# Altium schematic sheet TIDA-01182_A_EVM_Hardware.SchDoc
size 431 x 279 mm; Date: Not shown in title block; ApprovedBy: Not shown in title block; CheckedBy: Not shown in title block; Author: Not shown in title block; CompanyName: Not shown in title block; DrawnBy: Gordon Varney; Engineer: Not shown in title block; Organization: Not shown in title block; Address1: Not shown in title block; Address2: Not shown in title block; Address3: Not shown in title block; Address4: Not shown in title block; DocumentNumber: 1; Revision: Use project parameter SCH_Rev; SheetNumber: 4; SheetTotal: 4; PageSetup: Record=PageOptions¦CenterHorizontal=True¦CenterVertical=True¦PrintScale=1.00¦XCorrection=1.00¦YCorrection=1.00¦PrintKind=0¦BorderSize=5000000¦LeftOffset=0¦BottomOffset=0¦Orientation=2¦PaperLength=1000¦PaperWidth=1000¦Scale=100¦PaperSource=15¦PrintQuality=600¦MediaType=1¦DitherType=10¦PaperKind=Letter¦PrintScaleMode=1
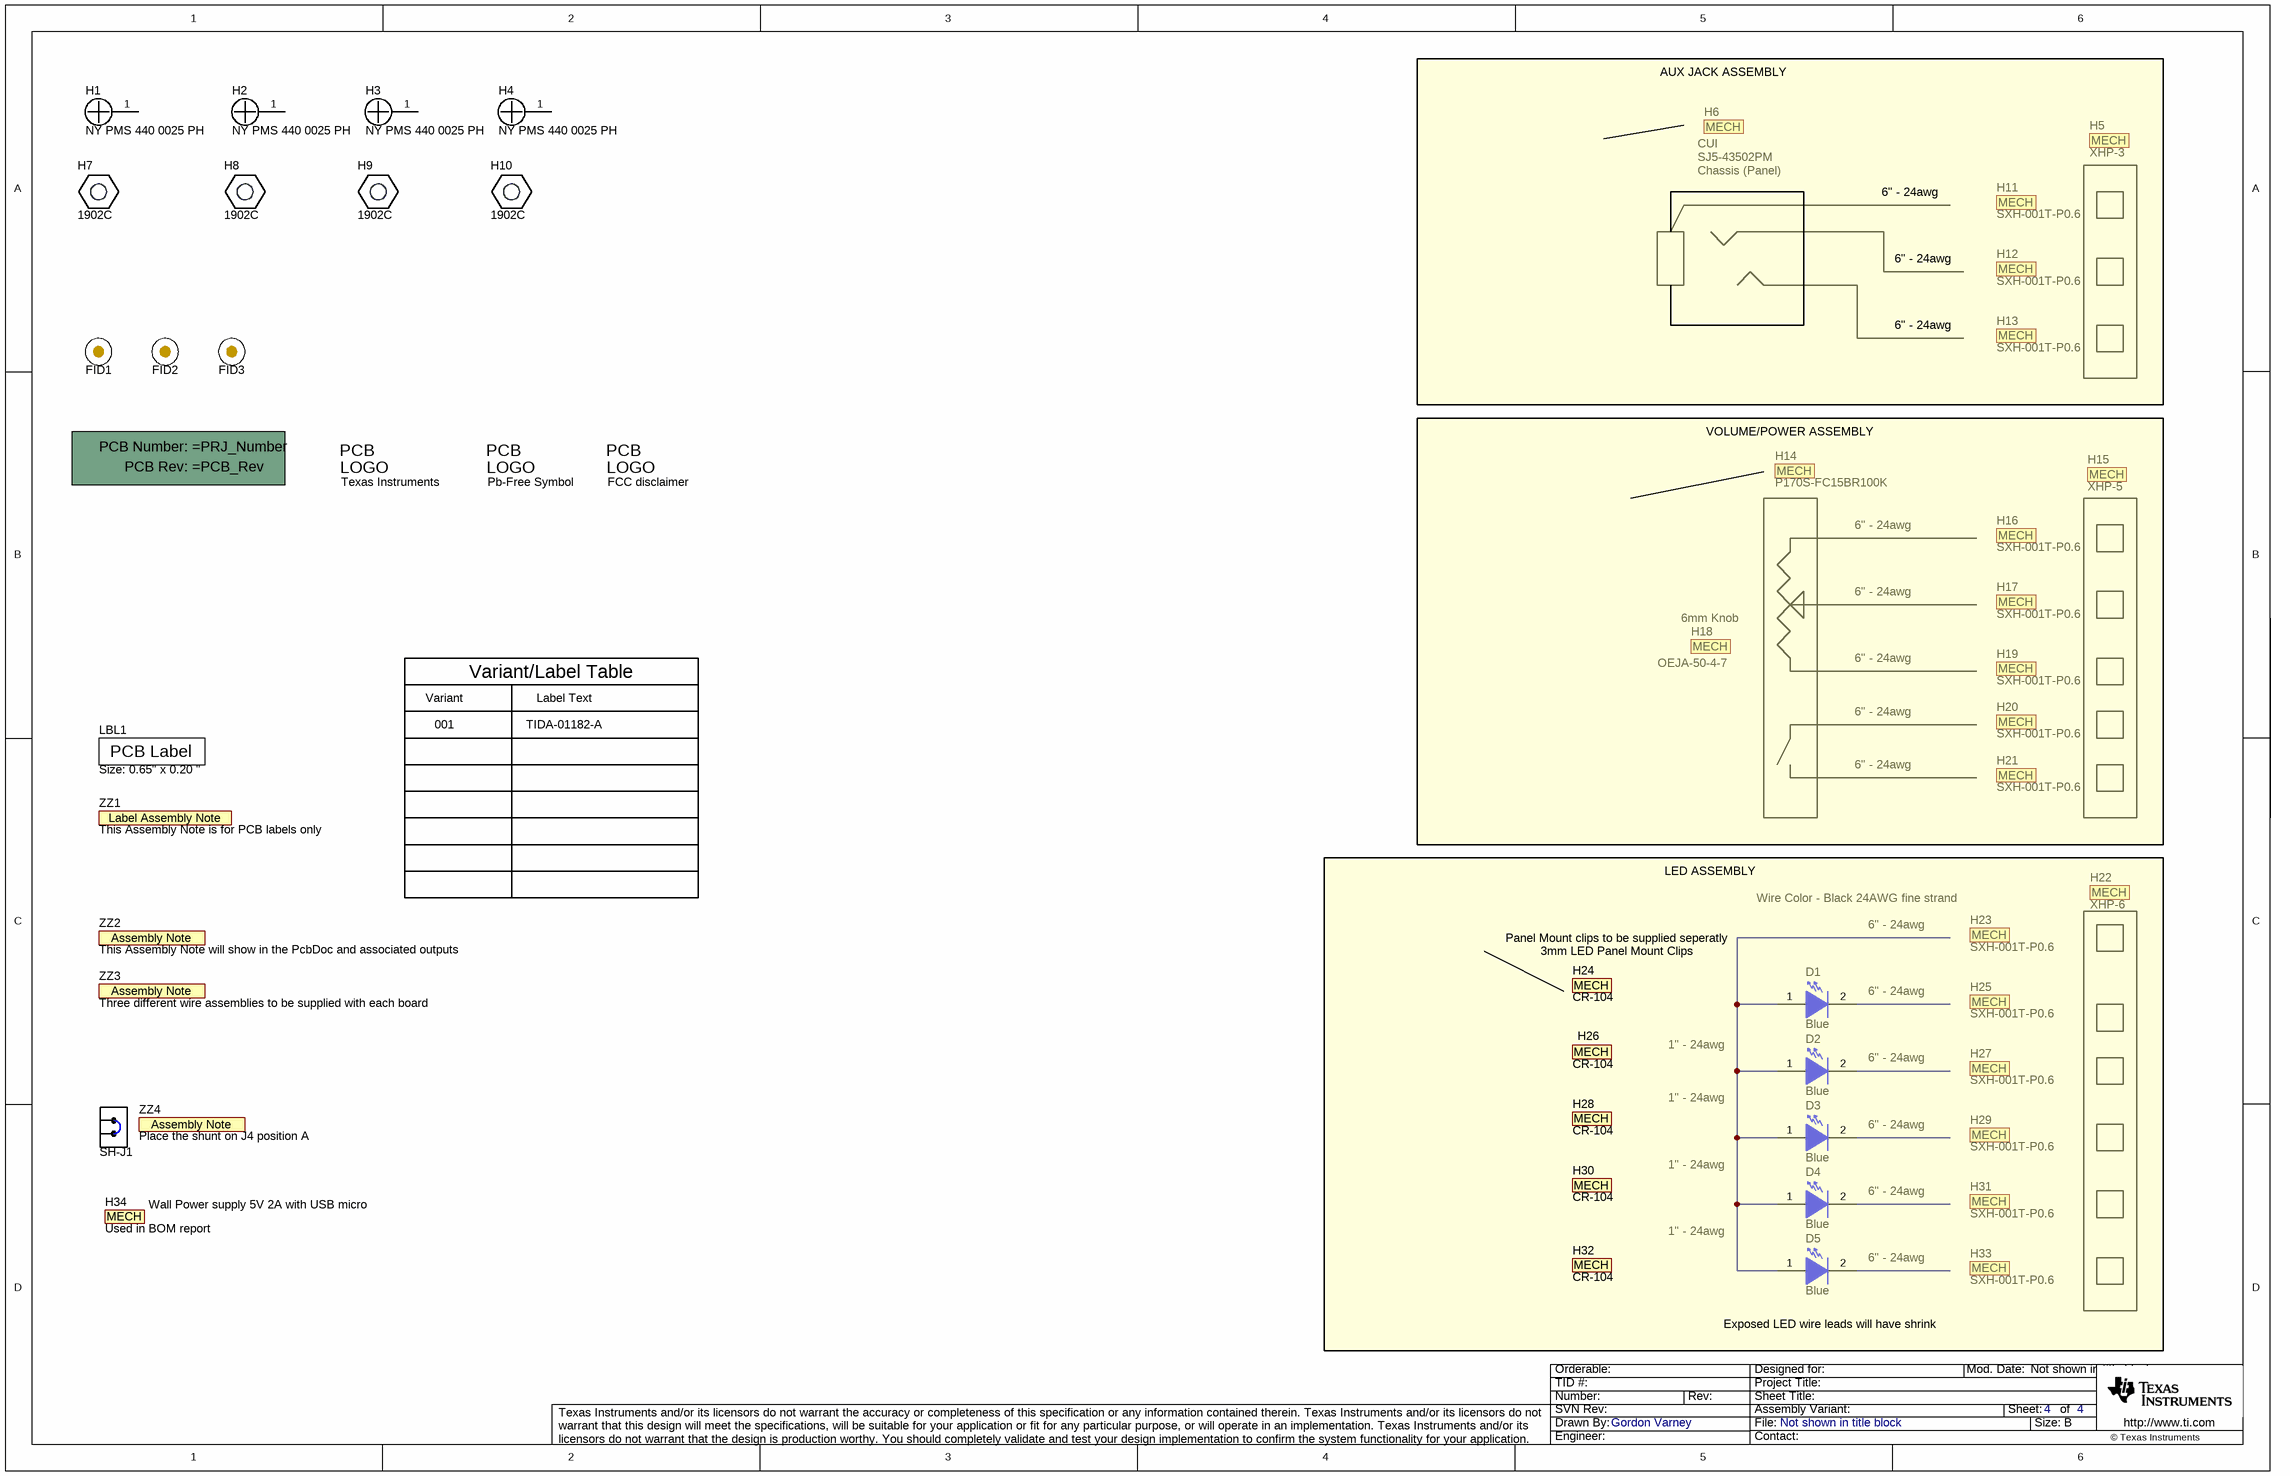
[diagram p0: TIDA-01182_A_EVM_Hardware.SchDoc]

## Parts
!PCB1  Printed Circuit Board  (value not drawn)  (mechanical)
D1  value Blue  [WP710A10_Blue]  (hidden comment: WP710A10LVBC/D)
D2  value Blue  [WP710A10_Blue]  (hidden comment: WP710A10LVBC/D)
D3  value Blue  [WP710A10_Blue]  (hidden comment: WP710A10LVBC/D)
D4  value Blue  [WP710A10_Blue]  (hidden comment: WP710A10LVBC/D)
D5  value Blue  [WP710A10_Blue]  (hidden comment: WP710A10LVBC/D)
FID1  Fiducial  [Fiducial10-30]  (value not drawn)
FID2  Fiducial  [Fiducial10-30]  (value not drawn)
FID3  Fiducial  [Fiducial10-30]  (value not drawn)
H1  NY PMS 440 0025 PH  [NY PMS 440 0025 PH]
H2  NY PMS 440 0025 PH  [NY PMS 440 0025 PH]
H3  NY PMS 440 0025 PH  [NY PMS 440 0025 PH]
H4  NY PMS 440 0025 PH  [NY PMS 440 0025 PH]
H5  XHP-3  (mechanical)
H6  SJ5-43502PM  PackageReference: Chassis (Panel)  Manufacturer: CUI  (mechanical)
H7  1902C  [Keystone_1902C]
H8  1902C  [Keystone_1902C]
H9  1902C  [Keystone_1902C]
H10  1902C  [Keystone_1902C]
H11  SXH-001T-P0.6  (mechanical)
H12  SXH-001T-P0.6  (mechanical)
H13  SXH-001T-P0.6  (mechanical)
H14  P170S-FC15BR100K  (mechanical)
H15  XHP-5  (mechanical)
H16  SXH-001T-P0.6  (mechanical)
H17  SXH-001T-P0.6  (mechanical)
H18  OEJA-50-4-7  (mechanical)
H19  SXH-001T-P0.6  (mechanical)
H20  SXH-001T-P0.6  (mechanical)
H21  SXH-001T-P0.6  (mechanical)
H22  XHP-6  (mechanical)
H23  SXH-001T-P0.6  (mechanical)
H24  CR-104  (mechanical)
H25  SXH-001T-P0.6  (mechanical)
H26  CR-104  (mechanical)
H27  SXH-001T-P0.6  (mechanical)
H28  CR-104  (mechanical)
H29  SXH-001T-P0.6  (mechanical)
H30  CR-104  (mechanical)
H31  SXH-001T-P0.6  (mechanical)
H32  CR-104  (mechanical)
H33  SXH-001T-P0.6  (mechanical)
H34  Used in BOM report  (mechanical)
LBL1  Size: 0.65" x 0.20 "  [Label_650x200]
Logo1  Texas Instruments  [TI_Stacked_SolderMask_Medium]  (no BOM)
Logo2  Pb-Free Symbol  [Pb-Free_Overlay_Medium]  (no BOM)
Logo3  FCC disclaimer  [FCC_disclaimer]  (no BOM)
SH-J1  969102-0000-DA  [SNT-100-BK-G]  (value not drawn)
ZZ1  This Assembly Note is for PCB labels only  [AssemblyNoteLabel]  (no BOM)
ZZ2  This Assembly Note will show in the PcbDoc and associated outputs  [AssemblyNote]  (no BOM)
ZZ3  Three different wire assemblies to be supplied with each board  [AssemblyNote]  (no BOM)
ZZ4  Place the shunt on J4 position A  [AssemblyNote]  (no BOM)

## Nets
NetD1_1: D1.1(A) D2.1(A) D3.1(A) D4.1(A) D5.1(A)

Not connected (* = marked no-connect by the designer): D1 2(K); D2 2(K); D3 2(K); D4 2(K); D5 2(K); H1 1; H2 1; H3 1; H4 1

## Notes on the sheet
- (near H6) AUX JACK ASSEMBLY
- 6" - 24awg
- (near H14) VOLUME/POWER ASSEMBLY
- (near H18) 6mm Knob
- Variant
- Variant/Label Table
- Label Text
- 001
- TIDA-01182-A
- LED ASSEMBLY
- (near H23) Wire Color - Black 24AWG fine strand
- (near H24) 3mm LED Panel Mount Clips
- (near H24) Panel Mount clips to be supplied seperatly
- 1" - 24awg
- (near H34) Wall Power supply 5V 2A with USB micro
- Exposed LED wire leads will have shrink

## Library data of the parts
!PCB1 = PCB: Manufacturer: Any; SymbolCreator: a0412235
D1-D5 = WP710A10LVBC/D: LED, Blue, TH; Manufacturer: Kingbright; Type: InGaN; Vf_V: 2.65; Value2: 2.65V; Io_A: 0.002; Vr_V: 5; Ir_A: 5e-005; Tjmax_C: 85; Power_TotalModule: 0.09; Value1: 0.09W; Angle: 20; SizeAreaWB_mm2: 17.64; SizeArea_mm2: 10.24; SizeX_mm: 3.2; SizeZ_mm: 10.5; U/M: EA
FID1-FID3 = Fiducial: Fiducial mark.  There is nothing to buy or mount.; SymbolCreator: codlsc
H1-H4 = NY PMS 440 0025 PH: Machine Screw, Round, #4-40 x 1/4, Nylon, Philips panhead; Manufacturer: B&F Fastener Supply; CompType: Hardware; SymbolCreator: codlsc; U/M: EA
H5 = XHP-3: CONN HOUSING 2.5MM XH 3POS; Manufacturer: JST Manufacturing; SymbolCreator: codlsc
H6 H34 = MechPart: Will add component to BOM.  Useful for cables, nuts, etc. not in libraries; SymbolCreator: codlsc; CompType: Mechanical; U/M: EA
H7-H10 = 1902C: Standoff, Hex, 0.5"L #4-40 Nylon; Manufacturer: Keystone; CompType: Hardware; SymbolCreator: a0412235
H11-H13 H16 H17 H19-H21 H23 H25 H27 H29 H31 H33 = SXH-001T-P0.6: CONN TERM CRIMP XH 22-28AWG; Manufacturer: JST Manufacturing; SymbolCreator: codlsc; CompType: Connector Terminal
H14 = P170S-FC15BR100K: 17mm Rotary Potentiometer, 100k Ohm, 0.1W, Solder Lugs, Panel Mount; Manufacturer: TT Electronics/IRC; SymbolCreator: codlsc
H15 = XHP-5: CONN HOUSING 2.5MM XH 5POS; Manufacturer: JST Manufacturing; SymbolCreator: codlsc
H18 = MechPart: Will add component to BOM.  Useful for cables, nuts, etc. not in libraries; Manufacturer: Kilo International; SymbolCreator: codlsc; CompType: Mechanical; U/M: EA
H22 = XHP-6: CONN HOUSING 2.5MM XH 6POS; Manufacturer: JST Manufacturing; SymbolCreator: codlsc
H24 H26 H28 H30 H32 = MechPart: Will add component to BOM.  Useful for cables, nuts, etc. not in libraries; Manufacturer: Bivar; SymbolCreator: codlsc; CompType: Mechanical; U/M: EA
LBL1 = THT-14-423-10: Thermal Transfer Printable Labels, 0.650" W x 0.200" H - 10,000 per roll; Manufacturer: Brady; SymbolCreator: a0412235; CompType: Label
Logo1 = TI_Logo: Texas Instrument Corporate Signature; SymbolCreator: a0412235
Logo2 = Pb-Free: SymbolCreator: a0412235
Logo3 = FCC_disclaimer: SymbolCreator: a0412235
SH-J1 = 969102-0000-DA: Shunt, 100mil, Gold plated, Black; Manufacturer: 3M; Alternate Manufacturer: Samtec; Value: 1x2; Note: You can "mate" this to a header by matching the designator.  i.e. use SH-J3 for header J3
ZZ1 = AssemblyNoteLabel: SymbolCreator: a0412235
ZZ2-ZZ4 = AssemblyNote: SymbolCreator: codlsc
